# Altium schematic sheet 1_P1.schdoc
size 604 x 431 mm; Symbol: Sheet-Symbol_A0; Device: Sheet-Symbol_A0; Company: 嘉立创EDA; Version: V1.0; Page Size: A0; @Project Name: MX无人机; @Page Count: 2; @Update Date: 2025-02-25; @Create Date: 2025-02-11; @Schematic Name: Schematic4; @Page No: 1; @Page Name: P1; @Board Name: 遥控; @Create Time: 20:46:43; @Update Time: 23:36:15
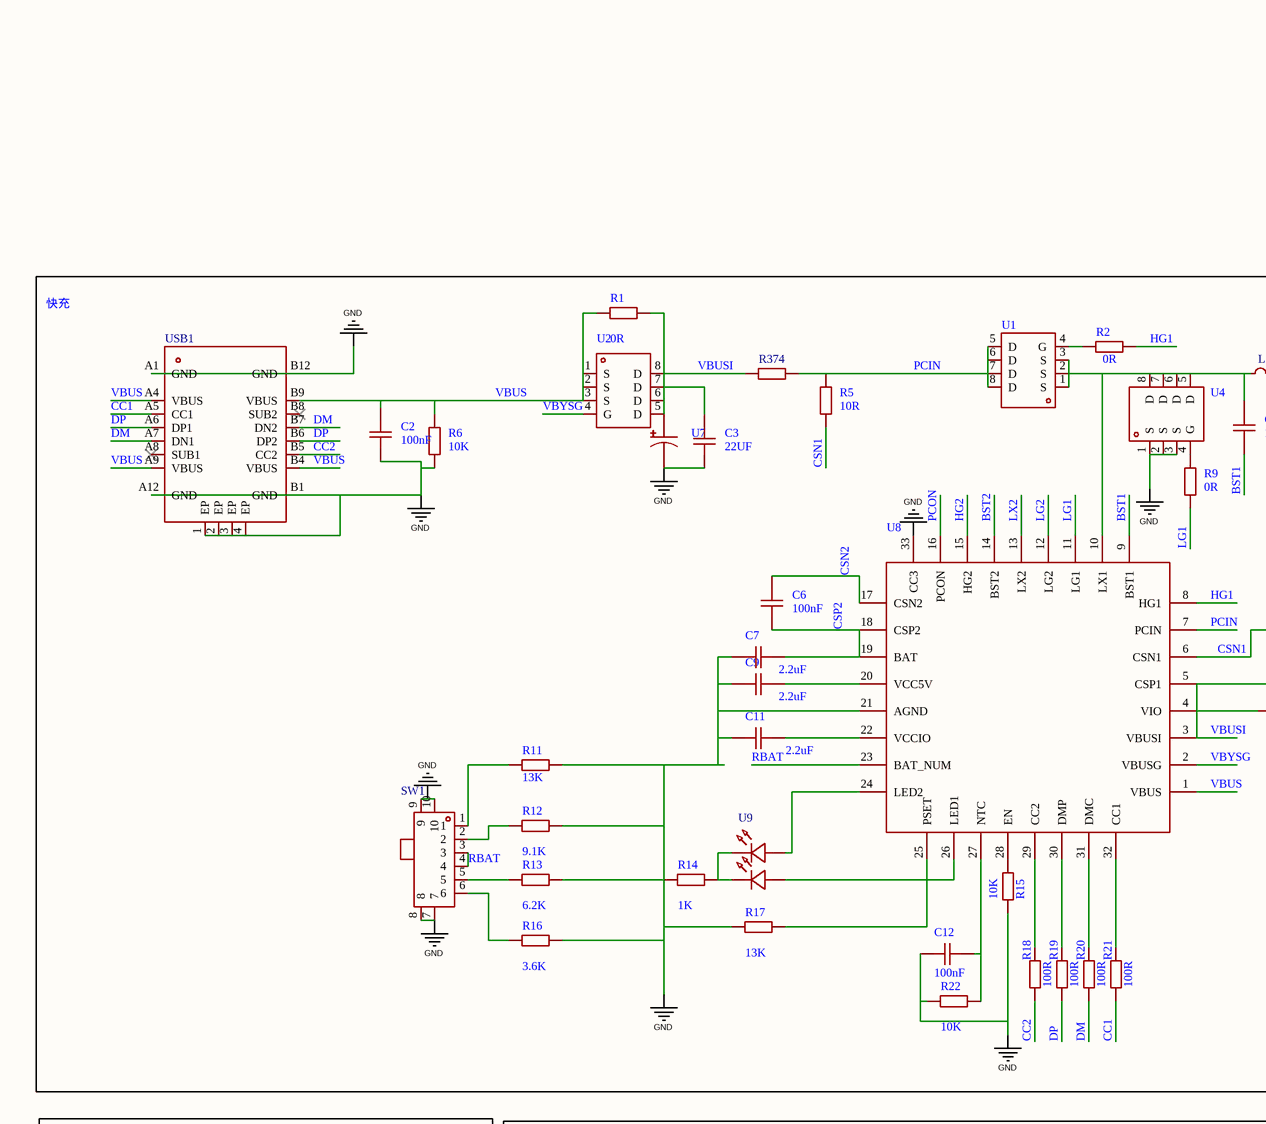
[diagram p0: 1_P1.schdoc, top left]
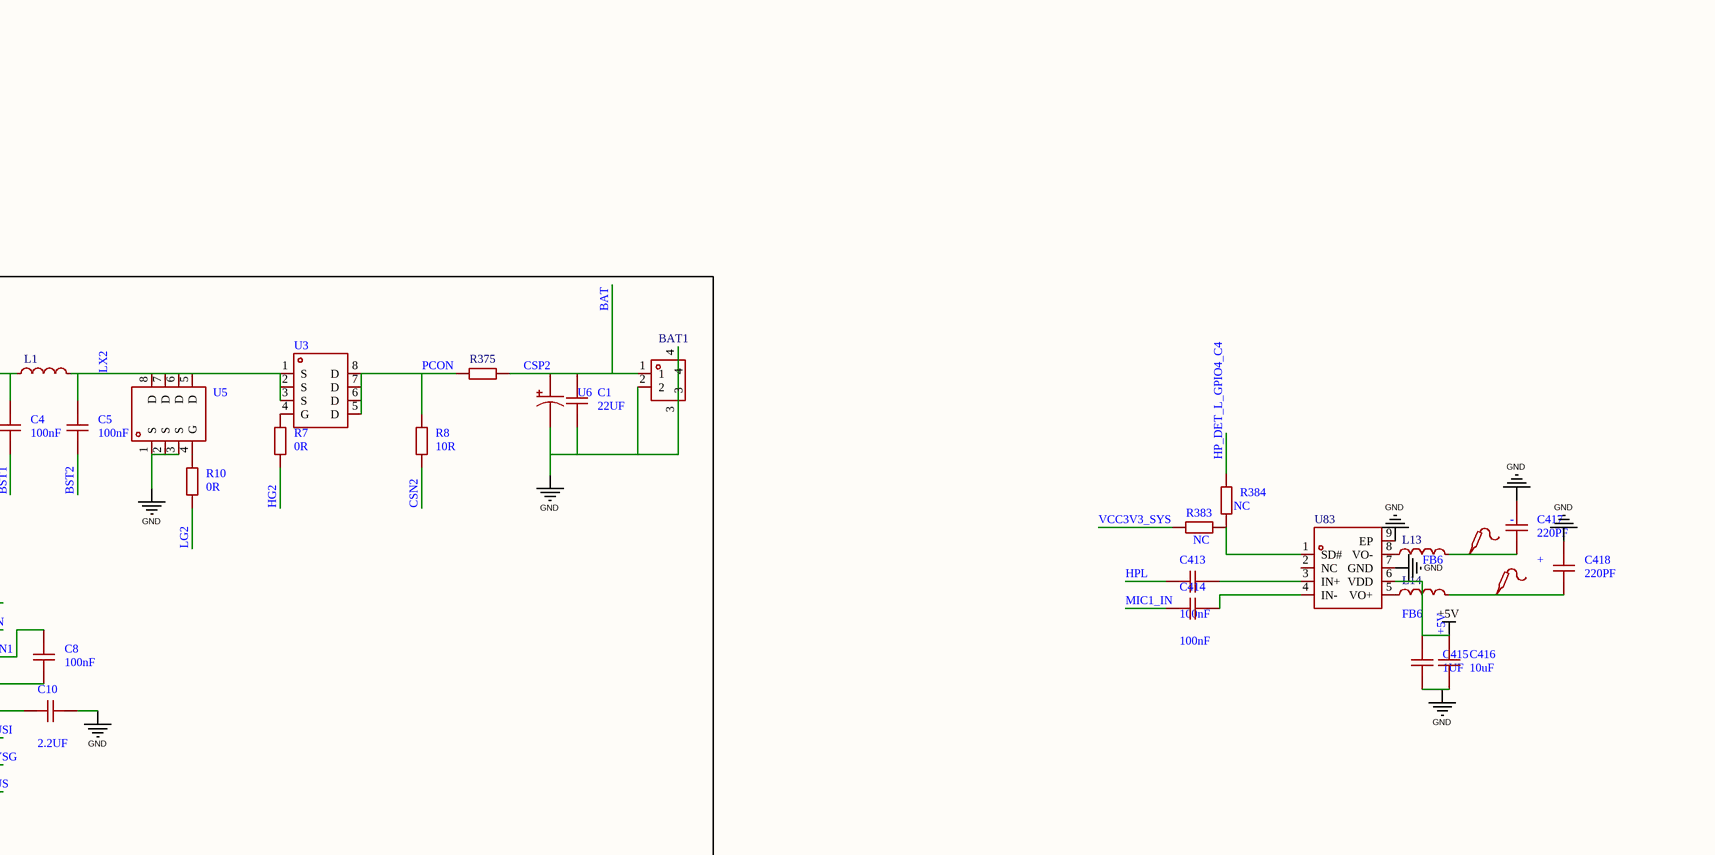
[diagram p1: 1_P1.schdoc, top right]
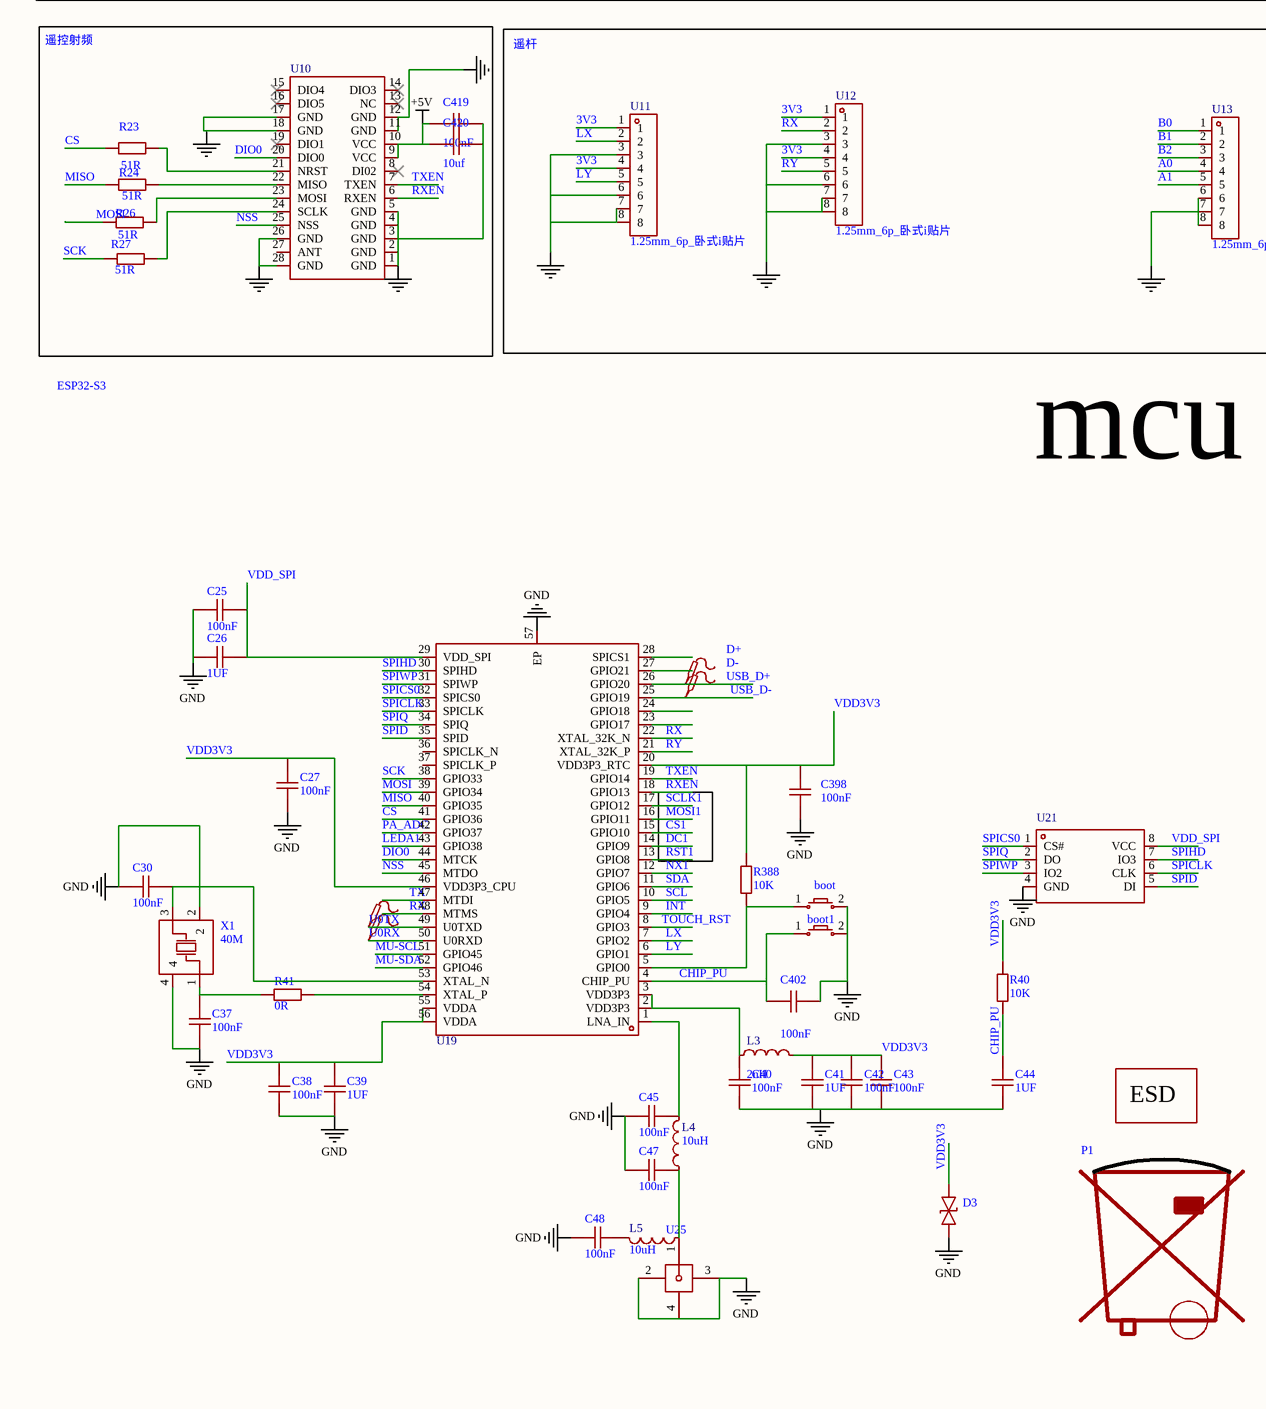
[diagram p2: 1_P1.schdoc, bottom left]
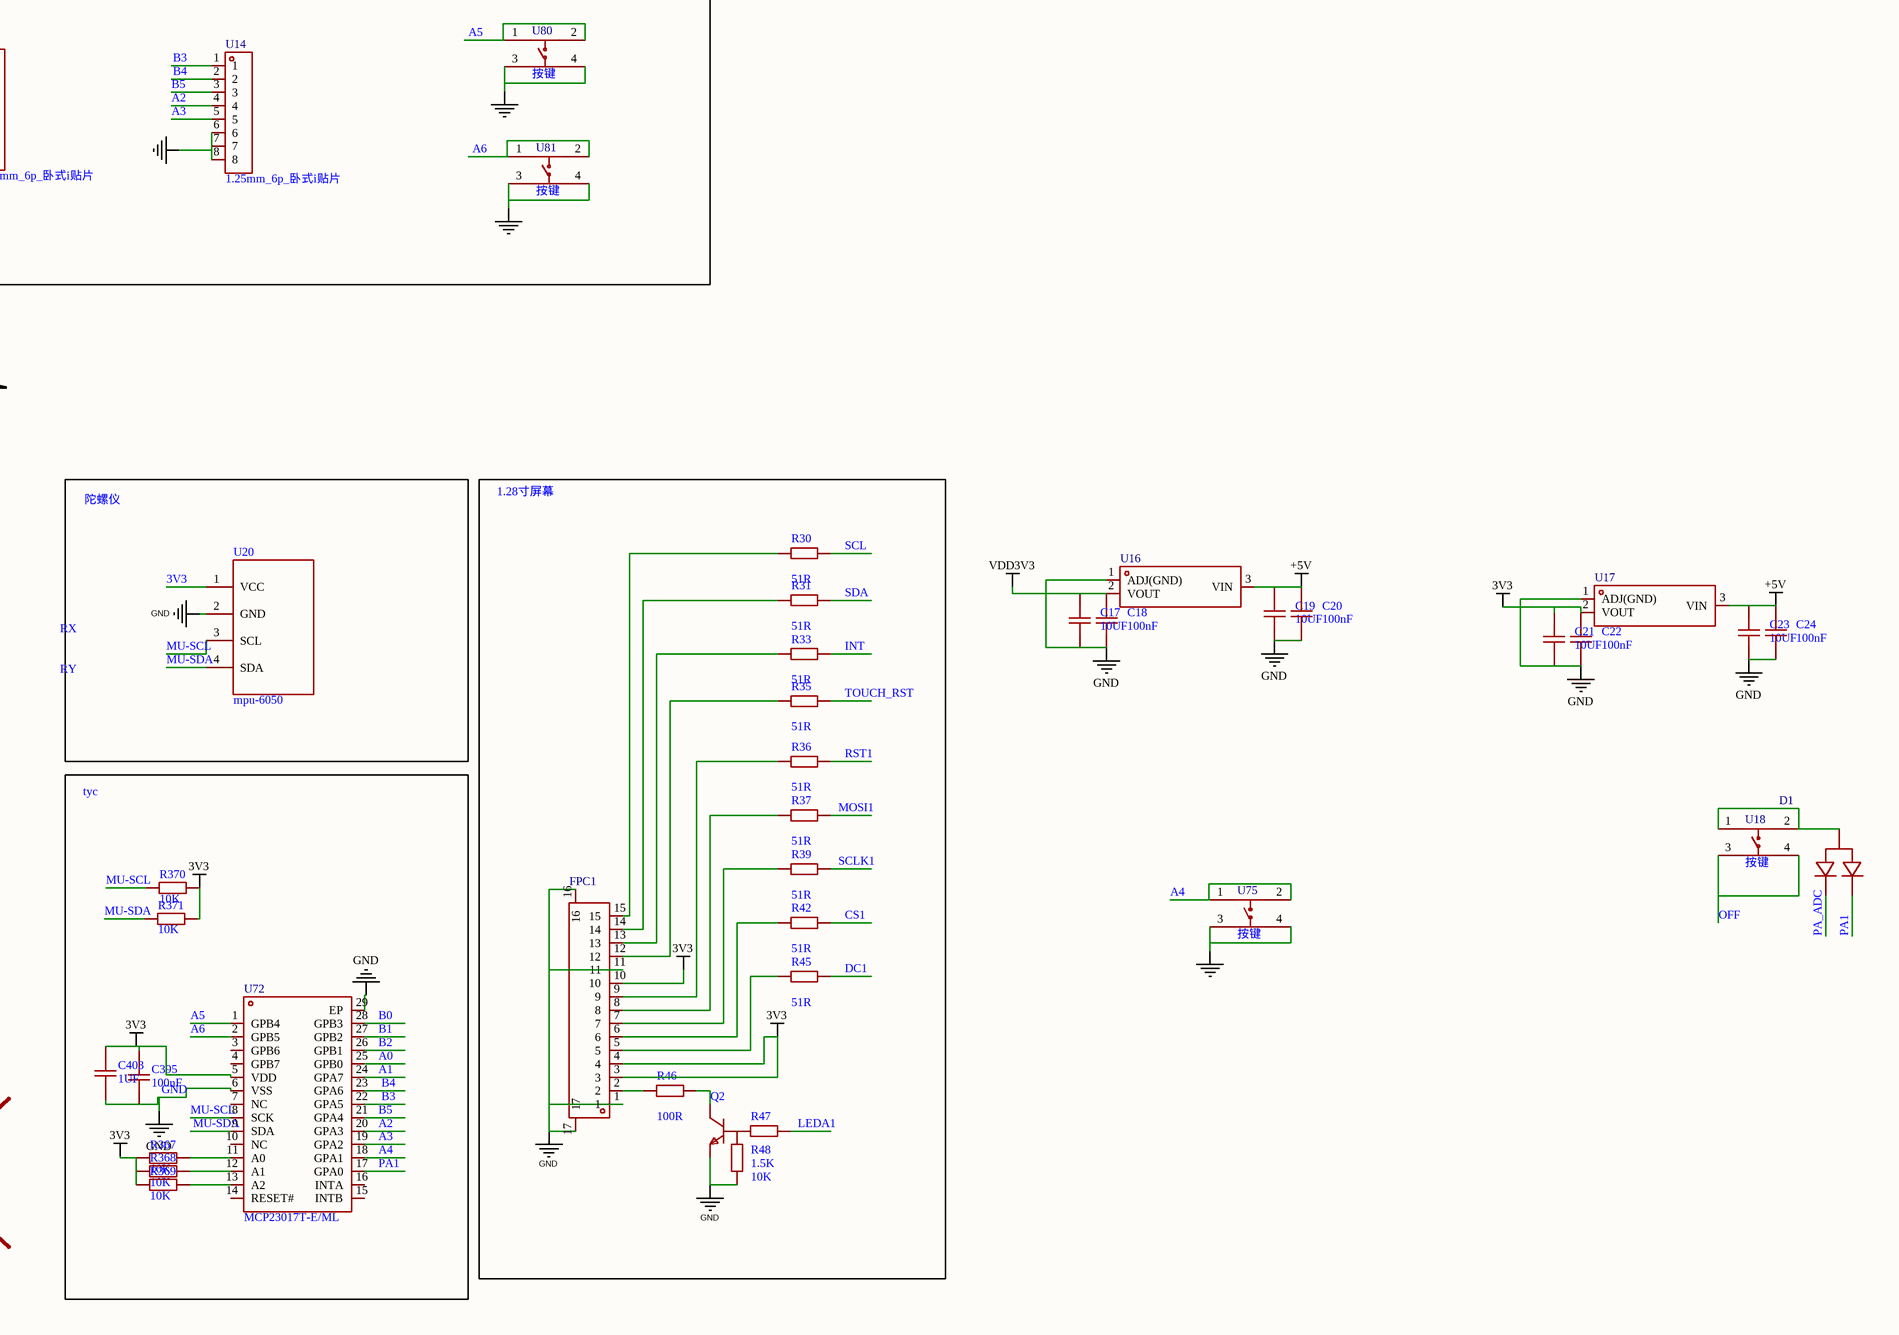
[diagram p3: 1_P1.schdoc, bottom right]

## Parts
+  (no value)  [Test-Point-0.5mm]
-  (no value)  [Test-Point-0.5mm]
BAT1  XH2.54-2P  [CONN-SMD_2P-P2.50-WT]  (value not drawn)
boot  (no value)  [Key_SMD_3x4x2]
boot1  (no value)  [Key_SMD_3x4x2]
C1  22UF  [C0805]
C2  100nF  [C0603]
C3  22UF  [C0805]
C4  100nF  [C0603]
C5  100nF  [C0603]
C6  100nF  [C0603]
C7  2.2uF  [C0603]
C8  100nF  [C0603]
C9  2.2uF  [C0603]
C10  2.2UF  [C0603]
C11  2.2uF  [C0603]
C12  100nF  [C0603]
C17  10UF  [C0603]
C18  100nF  [C0603]
C19  10UF  [C0603]
C20  100nF  [C0603]
C21  10UF  [C0603]
C22  100nF  [C0603]
C23  10UF  [C0603]
C24  100nF  [C0603]
C25  100nF  [C0402]
C26  1UF  [C0402]
C27  100nF  [C0402]
C30  100nF  [C0402]
C37  100nF  [C0402]
C38  100nF  [C0402]
C39  1UF  [C0402]
C40  100nF  [C0402]
C41  1UF  [C0402]
C42  100nF  [C0402]
C43  100nF  [C0402]
C44  1UF  [C0402]
C45  100nF  [C0402]
C47  100nF  [C0402]
C48  100nF  [C0402]
C395  100nF  [C0402]
C398  100nF  [C0402]
C402  100nF  [C0402]
C403  1UF  [C0402]
C413  100nF  [C0402]
C414  100nF  [C0402]
C415  1UF  [C0603]
C416  10uF  [C0603]
C417  220PF  [C0402]
C418  220PF  [C0402]
C419  100nF  [C0603]
C420  10uf  [C0603]
D1  BAT54A,215  [SOT-23-3_L3.0-W1.7-P0.95-LS2.9-BR]  (value not drawn)
D3  ESD5Z5V0C  [SOD-523_L1.2-W0.8-LS1.6-BI]  (value not drawn)
D+  (no value)  [Test-Point-0.5mm]
D-  (no value)  [Test-Point-0.5mm]
FPC1  GT-F0512SR18-15S0101  [FPC-SMD_15P-P0.50_GT-F0512SR18-15S0101]  (value not drawn)
L1  NR8040T330M  [IND-SMD_L8.0-W8.0]  (value not drawn)
L3  2nH  [L0603]
L4  10uH  [L0402]
L5  10uH  [L0402]
L13  FB6  [L0603]
L14  FB6  [L0603]
P1  (no value)  [垃圾桶LOGO COPY]
Q2  (no value)  [S8050_SOT-23]
R1  0R  [R1206]
R2  0R  [R0603]
R5  10R  [R0603]
R6  10K  [R0603]
R7  0R  [R0603]
R8  10R  [R0603]
R9  0R  [R0603]
R10  0R  [R0603]
R11  13K  [R0603]
R12  9.1K  [R0603]
R13  6.2K  [R0603]
R14  1K  [R0603]
R15  10K  [R0603]
R16  3.6K  [R0603]
R17  13K  [R0603]
R18  100R  [R0603]
R19  100R  [R0603]
R20  100R  [R0603]
R21  100R  [R0603]
R22  10K  [R0603]
R23  51R  [R0402]
R24  51R  [R0402]
R26  51R  [R0402]
R27  51R  [R0402]
R30  51R  [R0402]
R31  51R  [R0402]
R33  51R  [R0402]
R35  51R  [R0402]
R36  51R  [R0402]
R37  51R  [R0402]
R39  51R  [R0402]
R40  10K  [R0402]
R41  0R  [R0402]
R42  51R  [R0402]
R45  51R  [R0402]
R46  100R  [R0603]
R47  1.5K  [R0402]
R48  10K  [R0402]
R367  10K  [R0402]
R368  10K  [R0402]
R369  10K  [R0402]
R370  10K  [R0402]
R371  10K  [R0402]
R374  25121WF390MT4E  [r2512]  (value not drawn)
R375  25121WF390MT4E  [r2512]  (value not drawn)
R383  NC  [R0402]
R384  NC  [R0402]
R388  10K  [R0402]
RX  (no value)  [Test-Point-0.5mm]
SW1  MK-14C01-G2  [SW-SMD_DEALON_MK-14C01-G2]  (value not drawn)
TX  (no value)  [Test-Point-0.5mm]
U1  RU3030M3  [V-DFN3333-8_L3.3-W3.3-P0.65-BL]  (value not drawn)
U2  RU3030M3  [V-DFN3333-8_L3.3-W3.3-P0.65-BL]  (value not drawn)
U3  RU3030M3  [V-DFN3333-8_L3.3-W3.3-P0.65-BL]  (value not drawn)
U4  RU3030M3  [V-DFN3333-8_L3.3-W3.3-P0.65-BL]  (value not drawn)
U5  RU3030M3  [V-DFN3333-8_L3.3-W3.3-P0.65-BL]  (value not drawn)
U6  100uF贴片电解  [CAP-SMD_BD6.3-L6.6-W6.6-LS7.4-FD]  (value not drawn)
U7  100uF贴片电解  [CAP-SMD_BD6.3-L6.6-W6.6-LS7.4-FD]  (value not drawn)
U8  (no value)  [QFN-32_L5.0-W5.0-P0.50-BL-EP3.7]
U9  dualLED-红绿双色LED  [LED-SMD_4P-L1.6-W1.5]  (value not drawn)
U10  E32-400M30S  [WIRELM-SMD_E32-400M30S]  (value not drawn)
U11  1.25mm_6p_卧式i贴片  [CONN-SMD_6P-P1.25_HC-1.25-6PWT]
U12  1.25mm_6p_卧式i贴片  [CONN-SMD_6P-P1.25_HC-1.25-6PWT]
U13  1.25mm_6p_卧式i贴片  [CONN-SMD_6P-P1.25_HC-1.25-6PWT]
U14  1.25mm_6p_卧式i贴片  [CONN-SMD_6P-P1.25_HC-1.25-6PWT]
U16  LM1117-3.3V  [SOT-89-3_L4.5-W2.5-P1.50-LS4.1-BR]  (value not drawn)
U17  LM1117-3.3V  [SOT-89-3_L4.5-W2.5-P1.50-LS4.1-BR]  (value not drawn)
U18  按键  [SW-SMD_4P-L6.0-W6.0-P4.50-LS9.0-2]
U19  ESP32-S3  [QFN-56_L7.0-W7.0-P0.40-TL-EP4.0]  (value not drawn)
U20  (no value)  [mpu-6050]
U21  W25Q128JVSIQ  [SOIC-8_L5.3-W5.3-P1.27-LS8.0-BL]  (value not drawn)
U24  (no value)  [ESD]
U25  IPEX天线座,(贴片),特征阻抗50Ω,尺寸2.6mmx2.6mmx1.25mmROHS  [IPEX-SMD_HC-RF-IPEX0303-01]  (value not drawn)
U72  MCP23017T-E/ML  [QFN-28_L6.0-W6.0-P0.65-BL-EP3.7]
U75  按键  [SW-SMD_4P-L6.0-W6.0-P4.50-LS9.0-2]
U80  按键  [SW-SMD_4P-L6.0-W6.0-P4.50-LS9.0-2]
U81  按键  [SW-SMD_4P-L6.0-W6.0-P4.50-LS9.0-2]
U83  PAM8302AAYCR  [U-DFN3030-8_L3.0-W3.0-P0.65-BL-EP]  (value not drawn)
USB1  KH-TYPE-C-16P  [USB-C-SMD_KH-TYPE-C-16P]  (value not drawn)
X1  value 40M  [OSC-SMD_4P-L3.2-W2.5-BL_4]

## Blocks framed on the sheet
快充: BAT1 C1-C12 L1 R1 R2 R5-R22 R374 R375 SW1 U1-U9 USB1
遥控射频: C419 C420 R23 R24 R26 R27 U10
遥杆: U11-U14 U80 U81
陀螺仪: U20
1.28寸屏幕: FPC1 Q2 R30 R31 R33 R35-R37 R39 R42 R45-R48
tyc: C395 C403 R367-R371 U72

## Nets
3V3: C21.2 C22.2 C395.2 C403.2 FPC1.3 FPC1.4 FPC1.10 R367.1 R368.1 R369.1 R370.2 R371.2 U11.1 U11.4 U12.1 U12.4 U17.2(VOUT) U20.1(VCC) U72.5(VDD)
+5V: C19.2 C20.2 C23.2 C24.2 C415.2 C416.2 C419.2 C420.2 U10.9(VCC) U10.10(VCC) U16.3(VIN) U17.3(VIN) U83.6(VDD)
GND: BAT1.2 BAT1.3 BAT1.4 boot.2 boot1.2 C1.1 C2.1 C3.1 C7.1 C9.1 C10.2 C11.1 C12.2 C17.1 C18.1 C19.1 C20.1 C21.1 C22.1 C23.1 C24.1 C25.1 C26.1 C27.1 C30.2 C37.1 C38.1 C39.1 C40.1 C41.1 C42.1 C43.1 C44.1 C45.1 C47.1 C48.1 C395.1 C398.1 C402.2 C403.1 C415.1 C416.1 C417.2 C418.2 C419.1 C420.1 D3.1 FPC1.1 FPC1.11 FPC1.16 FPC1.17 Q2.2 R6.1 R11.1 R12.2 R13.2 R14.1 R15.1 R16.2 R17.1 R22.1 R48.1 SW1.7 SW1.8 SW1.9 SW1.10 U4.1(S) U4.2(S) U4.3(S) U5.1(S) U5.2(S) U5.3(S) U6.2 U7.2 U8.21(AGND) U8.33(CC3) U10.1(GND) U10.2(GND) U10.3(GND) U10.4(GND) U10.5(GND) U10.11(GND) U10.12(GND) U10.17(GND) U10.18(GND) U10.26(GND) U10.28(GND) U11.3 U11.6 U11.7 U11.8 U12.3 U12.6 U12.7 U12.8 U13.6 U13.7 U13.8 U14.6 U14.7 U14.8 U16.1(ADJ(GND)) U17.1(ADJ(GND)) U19.57(EP) U20.2(GND) U21.4(GND) U25.2 U25.3 U25.4 U72.6(VSS) U72.29(EP) U75.3 U75.4 U80.3 U80.4 U81.3 U81.4 U83.7(GND) U83.9(EP) USB1.1(EP) USB1.2(EP) USB1.3(EP) USB1.4(EP) USB1.A1(GND) USB1.A12(GND) USB1.B1(GND) USB1.B12(GND) X1.2 X1.4
VDD3V3: C17.2 C18.2 C27.2 C38.2 C39.2 C41.2 C42.2 C43.2 C398.2 D3.2 L3.2 R40.2 R388.2 U16.2(VOUT) U19.20(VDD3P3_RTC) U19.46(VDD3P3_CPU) U19.55(VDDA) U19.56(VDDA)
A0: U13.4 U72.25(GPB0)
A1: U13.5 U72.24(GPA7)
A2: U14.4 U72.20(GPA3)
A3: U14.5 U72.19(GPA2)
A4: U72.18(GPA1) U75.1 U75.2
A5: U72.1(GPB4) U80.1 U80.2
A6: U72.2(GPB5) U81.1 U81.2
B0: U13.1 U72.28(GPB3)
B1: U13.2 U72.27(GPB2)
B2: U13.3 U72.26(GPB1)
B3: U14.1 U72.22(GPA5)
B4: U14.2 U72.23(GPA6)
B5: U14.3 U72.21(GPA4)
BAT: BAT1.1 C1.2 C6.1 C7.2 R375.2 U6.1 U8.18(CSP2) U8.19(BAT)  [also labelled CSP2]
BST1: C4.1 U8.9(BST1)
BST2: C5.1 U8.14(BST2)
CC1: R21.1 USB1.A5(CC1)
CC2: R18.1 USB1.B5(CC2)
CHIP_PU: boot1.1 C44.2 C402.1 R40.1 U19.4(CHIP_PU)
CS: R23.2 U19.41(GPIO36)
CS1: R42.2 U19.15(GPIO10)
CSN1: C8.2 R5.1 U8.6(CSN1)
CSN2: C6.2 R8.1 U8.17(CSN2)
DC1: R45.2 U19.14(GPIO9)
DIO0: U10.20(DIO0) U19.44(MTCK)
DM: R20.1 USB1.A7(DN1) USB1.B7(DN2)
DP: R19.1 USB1.A6(DP1) USB1.B6(DP2)
HG1: R2.2 U8.8(HG1)
HG2: R7.1 U8.15(HG2)
HP_DET_L_GPIO4_C4: R384.2
HPL: C413.1
INT: R33.2 U19.9(GPIO4)
LEDA1: R47.2 U19.43(GPIO38)
LG1: R9.1 U8.11(LG1)
LG2: R10.1 U8.12(LG2)
LX: U11.2 U19.7(GPIO2)
LX2: C5.2 L1.2 U3.1(S) U3.2(S) U3.3(S) U5.5(D) U5.6(D) U5.7(D) U5.8(D) U8.13(LX2)
LY: U11.5 U19.6(GPIO1)
MIC1_IN: C414.1
MISO: R24.2 U19.40(GPIO35)
MOSI: R26.2 U19.39(GPIO34)
MOSI1: R37.2 U19.16(GPIO11)
MU-SCL: R370.1 U19.51(GPIO45) U20.3(SCL) U72.8(SCK)
MU-SDA: R371.1 U19.52(GPIO46) U20.4(SDA) U72.9(SDA)
NSS: U10.25(NSS) U19.45(MTDO)
NX1: U19.12(GPIO7)
OFF: U18.3 U18.4
PA1: D1.2(A) U72.17(GPA0)
PA_ADC: D1.1(A) U19.42(GPIO37)
PCIN: R5.2 R374.2 U1.5(D) U1.6(D) U1.7(D) U1.8(D) U8.7(PCIN)
PCON: R8.2 R375.1 U3.5(D) U3.6(D) U3.7(D) U3.8(D) U8.16(PCON)
RBAT: SW1.3 SW1.4 U8.23(BAT_NUM)
RST1: R36.2 U19.13(GPIO8)
RX: U12.2 U19.22(XTAL_32K_N)
RXEN: U10.6(RXEN) U19.18(GPIO13)
RY: U12.5 U19.21(XTAL_32K_P)
SCK: R27.2 U19.38(GPIO33)
SCL: R30.2 U19.10(GPIO5)
SCLK1: R39.2 U19.17(GPIO12)
SDA: R31.2 U19.11(GPIO6)
SPICLK: U19.33(SPICLK) U21.6(CLK)
SPICS0: U19.32(SPICS0) U21.1(CS#)
SPID: U19.35(SPID) U21.5(DI)
SPIHD: U19.30(SPIHD) U21.7(IO3)
SPIQ: U19.34(SPIQ) U21.2(DO)
SPIWP: U19.31(SPIWP) U21.3(IO2)
TOUCH_RST: R35.2 U19.8(GPIO3)
TXEN: U10.7(TXEN) U19.19(GPIO14)
U0RX: RX.1 U19.50(U0RXD)
U0TX: TX.1 U19.49(U0TXD)
USB_D+: D+.1 U19.26(GPIO20)
USB_D-: D-.1 U19.25(GPIO19)
VBUS: C2.2 R1.1 R6.2 U2.1(S) U2.2(S) U2.3(S) U8.1(VBUS) USB1.A4(VBUS) USB1.A9(VBUS) USB1.B4(VBUS) USB1.B9(VBUS)
VBUSI: C3.2 C8.1 C10.1 R1.2 R374.1 U2.5(D) U2.6(D) U2.7(D) U2.8(D) U7.1 U8.3(VBUSI) U8.4(VIO) U8.5(CSP1)
VBYSG: U2.4(G) U8.2(VBUSG)
VCC3V3_SYS: R383.1
VDD_SPI: C25.2 C26.2 U19.29(VDD_SPI) U21.8(VCC)
Net+_1: +.1 C418.1 L14.2
Net-_1: -.1 C417.1 L13.2
Netboot_1: boot.1 R388.1 U19.5(GPIO0)
NetC4_2: C4.2 L1.1 U1.1(S) U1.2(S) U1.3(S) U4.5(D) U4.6(D) U4.7(D) U4.8(D) U8.10(LX1)
NetC9_2: C9.2 U8.20(VCC5V)
NetC11_2: C11.2 U8.22(VCCIO)
NetC12_1: C12.1 R22.2 U8.27(NTC)
NetC30_1: C30.1 U19.53(XTAL_N) X1.3(OSC2)
NetC37_2: C37.2 R41.1 X1.1(OSC1)
NetC40_2: C40.2 L3.1 U19.2(VDD3P3) U19.3(VDD3P3)
NetC45_2: C45.2 L4.2 U19.1(LNA_IN)
NetC47_2: C47.2 L4.1 L5.1 U25.1
NetC48_2: C48.2 L5.2
NetC413_2: C413.2 U83.3(IN+)
NetC414_2: C414.2 U83.4(IN-)
NetD1_3: D1.3(C) U18.1 U18.2
NetFPC1_2: FPC1.2 R46.1
NetFPC1_5: FPC1.5 R45.1
NetFPC1_6: FPC1.6 R42.1
NetFPC1_7: FPC1.7 R39.1
NetFPC1_8: FPC1.8 R37.1
NetFPC1_9: FPC1.9 R36.1
NetFPC1_12: FPC1.12 R35.1
NetFPC1_13: FPC1.13 R33.1
NetFPC1_14: FPC1.14 R31.1
NetFPC1_15: FPC1.15 R30.1
NetL13_1: L13.1 U83.8(VO-)
NetL14_1: L14.1 U83.5(VO+)
NetQ2_1: Q2.1 R47.1 R48.2
NetQ2_3: Q2.3 R46.2
NetR2_1: R2.1 U1.4(G)
NetR7_2: R7.2 U3.4(G)
NetR9_2: R9.2 U4.4(G)
NetR10_2: R10.2 U5.4(G)
NetR11_2: R11.2 SW1.1
NetR12_1: R12.1 SW1.2
NetR13_1: R13.1 SW1.5
NetR14_2: R14.2 U9.1(K) U9.4(K)
NetR15_2: R15.2 U8.28(EN)
NetR16_1: R16.1 SW1.6
NetR17_2: R17.2 U8.25(PSET)
NetR18_2: R18.2 U8.29(CC2)
NetR19_2: R19.2 U8.30(DMP)
NetR20_2: R20.2 U8.31(DMC)
NetR21_2: R21.2 U8.32(CC1)
NetR23_1: R23.1 U10.21(NRST)
NetR24_1: R24.1 U10.22(MISO)
NetR26_1: R26.1 U10.23(MOSI)
NetR27_1: R27.1 U10.24(SCLK)
NetR41_2: R41.2 U19.54(XTAL_P)
NetR367_2: R367.2 U72.11(A0)
NetR368_2: R368.2 U72.12(A1)
NetR369_2: R369.2 U72.13(A2)
NetR383_2: R383.2 R384.1 U83.1(SD#)
NetU8_24: U8.24(LED2) U9.2(A)
NetU8_26: U8.26(LED1) U9.3(A)

Not connected (* = marked no-connect by the designer): U10 8(DI02)* 13(NC)* 14(DIO3)* 15(DIO4)* 16(DIO5)* 19(DIO1)* 27(ANT); U19 23(GPIO17) 24(GPIO18) 27(GPIO21) 28(SPICS1) 36(SPICLK_N) 37(SPICLK_P) 47(MTDI) 48(MTMS); U72 3(GPB6) 4(GPB7) 7(NC) 10(NC) 14(RESET#) 15(INTB) 16(INTA); U83 2(NC); USB1 A8(SUB1)* B8(SUB2)*

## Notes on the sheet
- ESP32-S3
- mcu
- Labels drawn without touching a wire or pin: RX, RY

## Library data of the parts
+ - D+ D- RX TX = Test-Point: Add into BOM: yes
BAT1 = XH2.54-2P: Add into BOM: yes
boot boot1 = Key_SMD_3x4x2: Symbol: 轻触按键x2; Convert to PCB: yes
C1 C3 = CAP_0805: Symbol: CapAcitance; Convert to PCB: yes
C2 C4-C12 C17-C24 C415 C416 C419 C420 = CAP_0603: Symbol: CapAcitance; Convert to PCB: yes
C25-C27 C30 C37-C45 C47 C48 C395 C398 C402 C403 C413 C414 C417 C418 = CAP_0402: Symbol: CapAcitance; Convert to PCB: yes
D1 = BAT54A,215: Manufacturer: Nexperia(安世); Add into BOM: yes; Diode Configuration: 1对共阳极; Reverse Voltage (Vr): 30V; Average Rectified Current (Io): 200mA; Reverse Leakage Current (Ir): 2uA@25V
D3 = ESD5Z5V0C_C129211: Add into BOM: yes; Reverse Stand-Off Voltage (Vrwm): 5V; Maximum Clamping Voltage: 12V; Peak Pulse Current (Ipp)@10/1000us: 4A; Breakdown Voltage: 5.6V
FPC1 = GT-F0512SR18-15S0101: Manufacturer: G-Switch(品赞); Add into BOM: yes; Locking Feature: 翻盖式; Number of Contacts: 15P; Pitch: 0.5mm; FFC, FCB Thickness: 0.3mm
L1 = NR8040T330M: Add into BOM: yes; Value: 4R7
L3 L13 L14 = L_0603: Symbol: SDFL1608S100KTF; Add into BOM: yes
L4 L5 = L_0402: Symbol: SDCL1005C10NJTDFM01; Add into BOM: yes
P1 = 回收和循环利用: Add into BOM: yes
Q2 = S8050_SOT_NPN: Symbol: NPN; Convert to PCB: yes
R1 = Res_1206: Symbol: 电阻; Add into BOM: yes
R2 R5-R22 R46 = Res_0603: Symbol: 电阻; Convert to PCB: yes
R23 R24 R26 R27 R30 R31 R33 R35-R37 R39-R42 R45 R47 R48 R367-R371 R383 R384 R388 = Res_0402: Symbol: 电阻; Convert to PCB: yes
R374 R375 = 25121WF390MT4E: Manufacturer: UNI-ROYAL(厚声); Add into BOM: yes
SW1 = MK-14C01-G2: Manufacturer: DEALON(德艺隆); Add into BOM: yes; Circuit: 单刀四掷; Actuator Style: 矩形柱状; Pin Style: SMD接片; Switch Length: 11.2mm; Switch Width: 2.7mm; Actuator Color: 黑色
U1-U5 = RU3030M3: Manufacturer: Ruichips(锐骏半导体); Add into BOM: yes
U6 U7 = 100uF贴片电解: Add into BOM: yes
U8 = IP2363: Add into BOM: yes
U9 = dualLED-红绿双色LED: Symbol: DUALLED-RED-BLUE-LED-1; Add into BOM: yes
U10 = E32-400M30S: Manufacturer: EBYTE(亿佰特); Add into BOM: yes
U11-U14 = 1.25mm_6p_卧式i贴片: Symbol: 1.25MM_6P_卧式I贴片_C9900015476; Add into BOM: yes
U16 U17 = LM1117-5V: Add into BOM: yes
U18 U75 U80 U81 = 按键: Symbol: SW; Add into BOM: yes
U19 = ESP32-S3: Manufacturer: ESPRESSIF(乐鑫); Add into BOM: yes
U20 = mpu-6050: Add into BOM: yes
U21 = W25Q128JVSIQ: Manufacturer: WINBOND(华邦); Symbol: W25Q128JVSIQTR; Add into BOM: yes; Memory Size: 128Mbit
U24 = ESD: Add into BOM: yes; _: 3
U25 = IPEX天线座,(贴片),特征阻抗50Ω,尺寸2.6mmx2.6mmx1.25mmROHS: Add into BOM: yes
U72 = MCP23017T-E/ML: Manufacturer: MICROCHIP(美国微芯); Add into BOM: yes; Number of I/O: 16; Interrupt Output: 有中断输出; Supply Voltage: 1.8V~5.5V
U83 = PAM8302AAYCR_C4990730: Manufacturer: DIODES(美台); Add into BOM: yes; Speaker Channels: 单声道; Output Power: 2.5Wx1@4Ω; Supply Voltage: 2V~5.5V
USB1 = KH-TYPE-C-16P: Manufacturer: kinghelm(金航标); Add into BOM: yes; Connector Type: Type-C; Gender: 母; Number of Contacts: 16P; Number of Ports: 1; Current Rating - Power (Max): 3A
X1 = 1N224000CC0BN: Manufacturer: KDS大真空; Add into BOM: yes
